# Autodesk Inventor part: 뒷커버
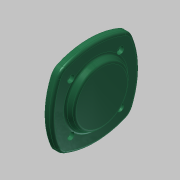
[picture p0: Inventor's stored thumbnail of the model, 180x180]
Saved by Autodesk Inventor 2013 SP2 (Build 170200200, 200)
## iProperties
Created: 2015-11
Part Number: 뒷커버
Material: 일반
Document SubType Name: Modeling
Designer: mduedu
Density: 1 g/cm^3
Author: mduedu
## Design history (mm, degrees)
sketch "스케치1"
  geometry: L1 (50, 50)-(-50, 50); L2 (-50, 50)-(-50, -50); L3 (-50, -50)-(50, -50); L4 (50, -50)-(50, 50); L5 (0, 50)-(0, -50); L6 (50, 0)-(-50, 0); A1 r 90 centre (-40, 0) between (40.415, -40.415) and (40.415, 40.415); A2 r 90 centre (40, 0) between (-40.415, 40.415) and (-40.415, -40.415); A3 r 90 centre (0, -40) between (40.415, 40.415) and (-40.415, 40.415); A4 r 90 centre (0, 40) between (-40.415, -40.415) and (40.415, -40.415); 2 further points
  constraints: 12 end point, 8 point on circle, 5 midpoint, 4 centre point, 2 horizontal alignment, 2 parallel, 2 perpendicular, 2 symmetric about line, 2 tangent, 2 vertical alignment, 1 equal radius, 1 horizontal, 2 other
  dimensions: "d0" = 100 distance of L3.end L1.start; "d2" = 90 radius of A1
extrude "돌출1" new body sketch "스케치1" distance "d3" = 8; taper "d4" = 0 deg
sketch "스케치2"
  geometry: C1 r 35 at (0, 0); 1 further point
  constraints: 1 centre point, 1 coincident
  dimensions: "d5" = 70 diameter of C1
extrude "돌출2" join sketch "스케치2" distance "d6" = 7; taper "d7" = -30 deg
sketch "스케치3"
  geometry: L1 (0, 0)-(0, 40); L2 (0, 0)-(-28.284, 28.284); A1 r 40 centre (0, 0) between (0, 40) and (-28.284, 28.284); 2 further points
  constraints: 4 end point, 2 coincident, 2 point on circle, 1 centre point, 1 vertical
  dimensions: "d8" = 80 diameter of A1; "d9" = 45 deg angle of L1 L2
hole "구멍1" sketch "스케치3" at (-28.284, 28.284) diameter "d11" = 4.5; stored, may be unused: countersink angle "d15" = 90 deg, drill point angle "d17" = 118 deg; dims "d12" = 6, "d13" = 8, "d14" = 4.4, "d16" = 8
sketch "스케치4"
  geometry: C1 r 35 at (0, 0); 1 further point
  constraints: 1 centre point, 1 coincident
  dimensions: "d21" = 70 diameter of C1
extrude "돌출3" join sketch "스케치4" distance "d23" = 12; taper "d24" = 0 deg
hole "구멍2" diameter "d27" = 30; stored, may be unused: countersink angle "d31" = 90 deg, drill point angle "d33" = 0 deg; dims "d25" = 10, "d26" = 10, "d28" = 6, "d29" = 40, "d30" = 12, "d32" = 15
fillet "모깎기2" dims "d35" = 15
fillet "모깎기3" dims "d36" = 3
fillet "모깎기4" dims "d37" = 3
fillet "모깎기5" dims "d38" = 0.3
chamfer "모따기1" distance "d39" = 1; stored, may be unused: second distance "d40" = 2, angle "d41" = 45 deg
node "솔리드1"
pattern_circular "원형 패턴1" dims angle "d19" = 360 deg
